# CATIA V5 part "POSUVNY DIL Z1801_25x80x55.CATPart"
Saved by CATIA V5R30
Part number: POSUVNY DIL VETSI
Bounding box of the stored display mesh (mm): x -55 to 0, y 0 to 25, z -43 to 43
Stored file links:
  C:\Users\ondra\Desktop\PŘÍLOHA P III\CATIA\POSUVNY DIL Z1801_25x80x55.CATPart
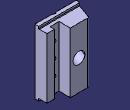
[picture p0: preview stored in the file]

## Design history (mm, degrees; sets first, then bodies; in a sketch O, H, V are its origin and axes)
Set1
  DatumSurface1 to DatumSurface34 "Z1801/25"
  Plane1: type Tangent, Support DatumSurface31, RefPoint vertex [face of DatumSurface24]
  Plane2: type Tangent, Support DatumSurface28, RefPoint vertex [face of DatumSurface24]
  Plane3: type Tangent, Support DatumSurface11, RefPoint vertex [face of DatumSurface10]
  Plane4: type Tangent, Support DatumSurface34, RefPoint vertex [face of DatumSurface26]
  Join1: Elements (DatumSurface1; DatumSurface2; DatumSurface3; DatumSurface4; DatumSurface5; DatumSurface6; DatumSurface7; DatumSurface8; DatumSurface9; DatumSurface10; DatumSurface11; DatumSurface12; DatumSurface13; DatumSurface14; DatumSurface15; DatumSurface16; DatumSurface17; DatumSurface18; DatumSurface19; DatumSurface20; DatumSurface21; DatumSurface22; DatumSurface23; DatumSurface24; DatumSurface25; DatumSurface26; DatumSurface27; DatumSurface28; DatumSurface29; DatumSurface30; DatumSurface31; DatumSurface32; DatumSurface33; DatumSurface34)
Body1 (main body)
  CloseSurface1: CloseElement Join1
  Sketch1, origin (87.0375, 1.7848, 0), H (0, 1, 0), V (-1, 0, 0), geometry linked from another document
  Pocket1: profile Sketch1, direction (0, 0, -1), through (limit type 6), opposite side through (limit type 6)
